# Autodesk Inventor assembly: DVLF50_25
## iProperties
Created: 2010-03
Part Number: DVLF50_25
Document SubType Name: Assembly
Designer: TB
Mass: 778.209 g
Surface Area: 1487.77 cm^2
Volume: 778.209 cm^3
Density: 1 g/cm^3
Description: KM DVLF 50/25 - 100 mm
Slaglengde: 100.000 mm
Author: TB
